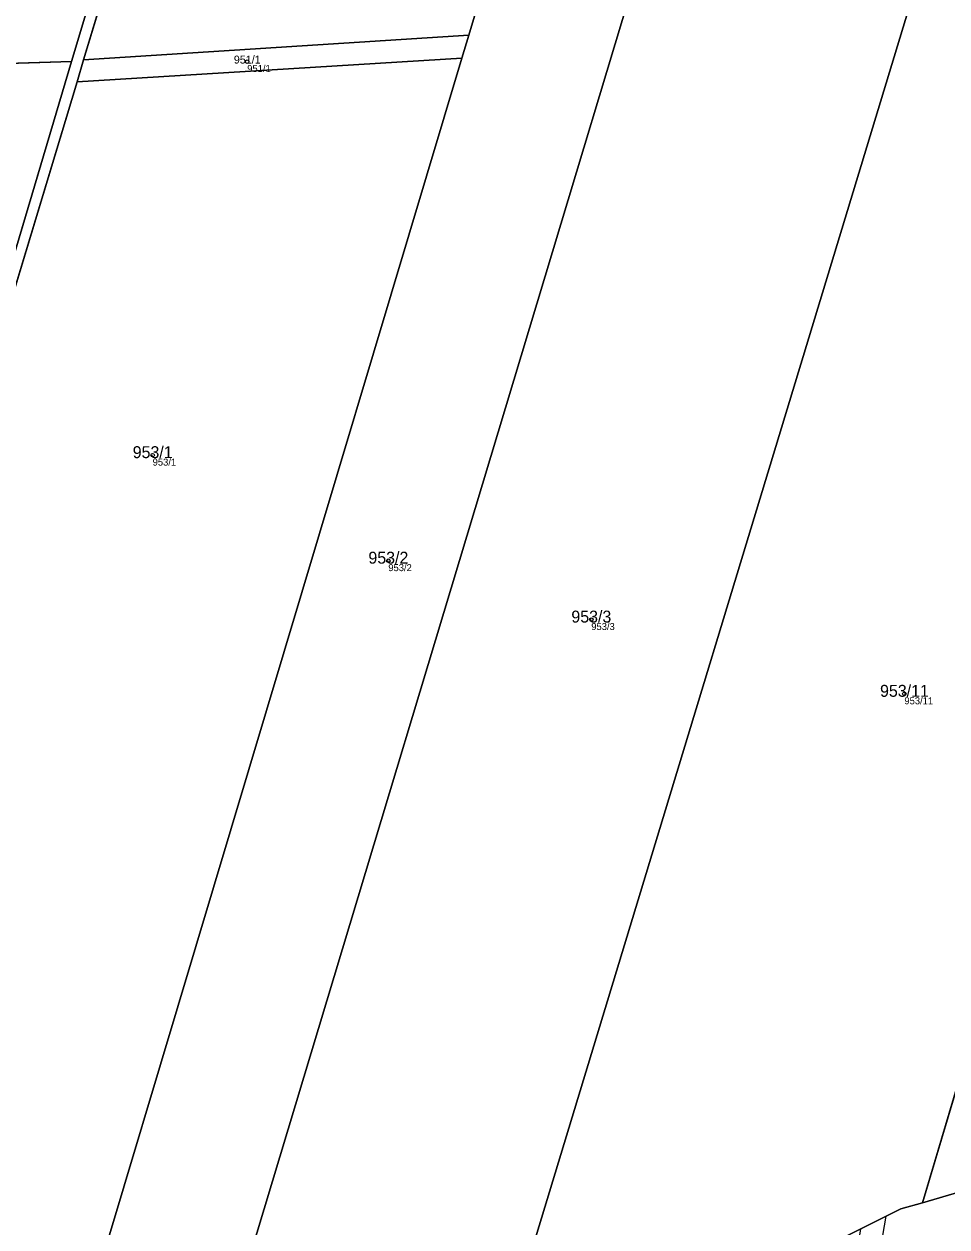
# Model space of a CAD drawing. Extents: x -603967 to -594699, y -1179315 to -1165625.
# Drawn here: x -597159.4 to -597028, y -1172835.4 to -1172664.1 of the extents above; entities that cross this region are included whole.
import ezdxf

# ---------------------------------------------------------------- set-up
doc = ezdxf.new("R2010")
doc.units = 0
for name, color, linetype in [('Definiční body', 7, 'Continuous'), ('Hranice parcel', 7, 'Continuous'), ('Parcelní čísla', 7, 'Continuous'), ('Polygon parcely', 7, 'Continuous'), ('Věcná břemena k části', 7, 'Continuous')]:
    doc.layers.add(name, color=color, linetype=linetype)

msp = doc.modelspace()

# ---------------------------------------------------------------- linework, layer by layer
at = {"layer": 'Definiční body'}
for centre in [(-597127.65, -1172669.45994), (-597141.12, -1172725.50994), (-597107.55, -1172740.53994), (-597078.64, -1172748.92994), (-597034.04, -1172759.49994)]:
    msp.add_circle(centre, 0.25, dxfattribs=at)
at = {"layer": 'Hranice parcel'}
for p, q in [((-597127.98, -1172593.36), (-597150.95, -1172669.23)), ((-597152.68, -1172669.43), (-597144.25, -1172641.45)), ((-596981.74, -1172664.88), (-597031.45, -1172831.97)), ((-597150.95, -1172669.23), (-597096.1, -1172665.68)), ((-597097.09, -1172668.97), (-597096.1, -1172665.68)), ((-597157.76, -1172871.57), (-597097.09, -1172668.97)), ((-597151.89, -1172672.35), (-597097.09, -1172668.97)), ((-597197.06, -1172670.81), (-597152.68, -1172669.43)), ((-597184.59, -1172776.79), (-597152.68, -1172669.43)), ((-597151.89, -1172672.35), (-597150.95, -1172669.23)), ((-597151.89, -1172672.35), (-597184.18, -1172779.24)), ((-597026.16, -1172830.43), (-597031.45, -1172831.97)), ((-597031.45, -1172831.97), (-597034.57, -1172832.87))]:
    msp.add_line(p, q, dxfattribs=at)
for points in [[(-597096.1, -1172665.68), (-597083.72, -1172624.35), (-597081.9, -1172619.48)], [(-597145.17, -1172899.03), (-597065.25, -1172633.8), (-597063.74, -1172628.93)], [(-597092.38, -1172856.05), (-597030.34, -1172651.68), (-597028.61, -1172647.14)], [(-597034.57, -1172832.87), (-597044.5, -1172837.85), (-597053.2, -1172845.48), (-597061.58, -1172854.05), (-597067.24, -1172865.47)]]:
    msp.add_lwpolyline(points, dxfattribs=at)
at = {"layer": 'Polygon parcely'}
for points in [[(-597144.25, -1172641.45), (-597152.68, -1172669.43), (-597184.59, -1172776.79), (-597184.18, -1172779.24), (-597151.89, -1172672.35), (-597150.95, -1172669.23), (-597127.98, -1172593.36), (-597129.63, -1172592.38), (-597130.13, -1172593.91), (-597137.2, -1172617.74)], [(-597081.9, -1172619.48), (-597111.9, -1172603.92), (-597127.98, -1172593.36), (-597150.95, -1172669.23), (-597096.1, -1172665.68), (-597083.72, -1172624.35)], [(-597065.25, -1172633.8), (-597063.74, -1172628.93), (-597081.9, -1172619.48), (-597083.72, -1172624.35), (-597096.1, -1172665.68), (-597097.09, -1172668.97), (-597157.76, -1172871.57), (-597146.71, -1172896.69), (-597145.17, -1172899.03)], [(-597136.59, -1172910.65), (-597113.34, -1172923.26), (-597092.38, -1172856.05), (-597030.34, -1172651.68), (-597028.61, -1172647.14), (-597063.74, -1172628.93), (-597065.25, -1172633.8), (-597145.17, -1172899.03), (-597139.09, -1172908.23)], [(-597200.14, -1172649.62), (-597197.06, -1172670.81), (-597152.68, -1172669.43), (-597144.25, -1172641.45)], [(-597092.38, -1172856.05), (-597067.24, -1172865.47), (-597061.58, -1172854.05), (-597053.2, -1172845.48), (-597044.5, -1172837.85), (-597034.57, -1172832.87), (-597031.45, -1172831.97), (-596981.74, -1172664.88), (-596992.13, -1172661.39), (-597018, -1172652.66), (-597028.61, -1172647.14), (-597030.34, -1172651.68)], [(-596971.11, -1172668.29), (-596980.29, -1172665.33), (-596981.74, -1172664.88), (-597031.45, -1172831.97), (-597026.16, -1172830.43), (-597019.28, -1172830.11)], [(-597097.09, -1172668.97), (-597096.1, -1172665.68), (-597150.95, -1172669.23), (-597151.89, -1172672.35)], [(-597161.11, -1172863.97), (-597157.76, -1172871.57), (-597097.09, -1172668.97), (-597151.89, -1172672.35), (-597184.18, -1172779.24), (-597177.97, -1172819.62), (-597173.01, -1172822.02), (-597166.05, -1172830.63)], [(-597184.59, -1172776.79), (-597152.68, -1172669.43), (-597197.06, -1172670.81), (-597200.46, -1172670.98), (-597200.39, -1172674.62)]]:
    msp.add_lwpolyline(points, close=True, dxfattribs=at)
msp.add_lwpolyline([(-597026.16, -1172830.43), (-597031.45, -1172831.97), (-597034.57, -1172832.87), (-597044.5, -1172837.85), (-597053.2, -1172845.48), (-597061.58, -1172854.05), (-597067.24, -1172865.47), (-597078.95, -1172902.08), (-597087.73, -1172930.92), (-597092.15, -1172943.27), (-597085.37, -1172945.09), (-597060.48, -1172867.37), (-597044.6, -1172846.07), (-597030.65, -1172838.75), (-597013.99, -1172836.28)], dxfattribs=at)
at = {"layer": 'Věcná břemena k části'}
msp.add_lwpolyline([(-597038.3, -1172849.12), (-597038.81, -1172846.84), (-597038.7, -1172846.13), (-597038.17, -1172842.7), (-597036.64, -1172833.91), (-597040.31, -1172835.75), (-597041.86, -1172844.63), (-597042.24, -1172848.11), (-597042.3, -1172848.7), (-597041.5, -1172850.64)], close=True, dxfattribs=at)

# ---------------------------------------------------------------- texts
at = {"layer": 'Definiční body'}
for s, p in [('951/1', (-597127.65, -1172670.949)), ('953/1', (-597141.12, -1172726.999)), ('953/2', (-597107.55, -1172742.029)), ('953/3', (-597078.64, -1172750.419)), ('953/11', (-597034.04, -1172760.989))]:
    msp.add_text(s, height=0.999996, dxfattribs=at).set_placement(p)
at = {"layer": 'Parcelní čísla'}
for s, height, p in [('951/1', 1.14, (-597129.551, -1172669.745)), ('953/1', 1.699998, (-597143.956, -1172725.935)), ('953/2', 1.699998, (-597110.386, -1172740.965)), ('953/3', 1.699998, (-597081.476, -1172749.355)), ('953/11', 1.699998, (-597037.506, -1172759.925))]:
    msp.add_text(s, height=height, dxfattribs=at).set_placement(p)

doc.saveas('drawing.dxf')
